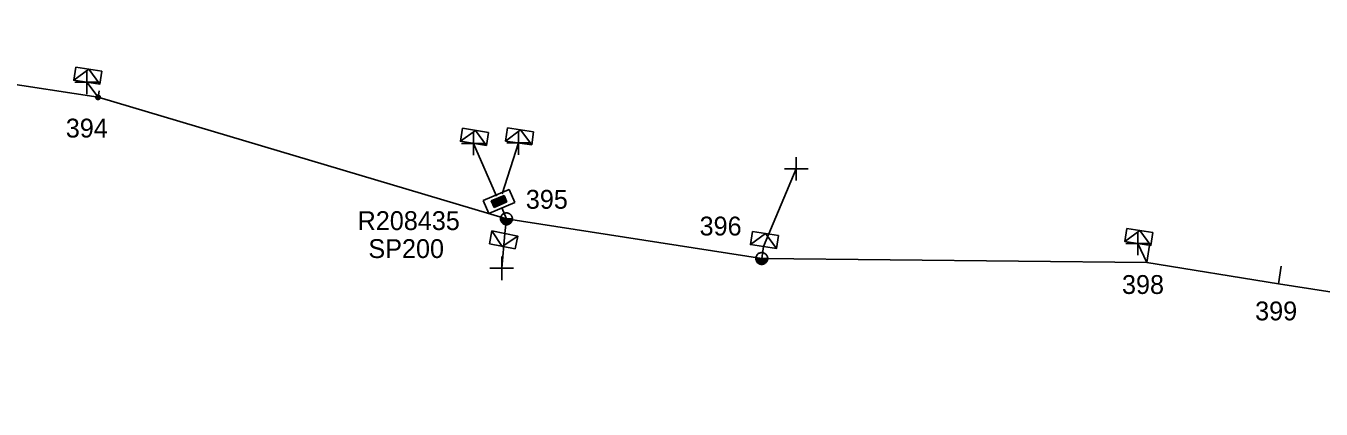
# Model space of a CAD drawing. Extents: x -540466 to -537383, y -1184038 to -1179972.
# Drawn here: x -539321 to -539252.2, y -1180550.2 to -1180529.9 of the extents above; entities that cross this region are included whole.
import ezdxf

# ---------------------------------------------------------------- set-up
doc = ezdxf.new("R2010")
doc.units = 0
for name, color, linetype in [('Vrstva 1', 7, 'Continuous'), ('Vrstva 13', 7, 'Continuous'), ('Vrstva 14', 7, 'Continuous'), ('Vrstva 2', 7, 'Continuous'), ('Vrstva 28', 7, 'Continuous'), ('Vrstva 29', 7, 'Continuous'), ('Vrstva 30', 7, 'Continuous'), ('Vrstva 31', 7, 'Continuous'), ('Vrstva 34', 7, 'Continuous'), ('Vrstva 50', 7, 'Continuous'), ('Vrstva 52', 7, 'Continuous'), ('Vrstva 54', 7, 'Continuous'), ('Vrstva 59', 7, 'Continuous'), ('Vrstva 8', 7, 'Continuous'), ('Vrstva 9', 7, 'Continuous')]:
    doc.layers.add(name, color=color, linetype=linetype)

# ---------------------------------------------------------------- blocks, each defined once
blk = doc.blocks.new('NN440')
at = {"layer": 'Vrstva 2'}
for points in [[(0.63, 0), (0.63, 0.06), (0.62, 0.13), (0.6, 0.19), (0.58, 0.25), (0.55, 0.31), (0.51, 0.37), (0.47, 0.42), (0.42, 0.46), (0.37, 0.51), (0.32, 0.54), (0.26, 0.57), (0.2, 0.59), (0.13, 0.61), (0.07, 0.62), (0, 0.63), (-0.06, 0.62), (-0.13, 0.61), (-0.19, 0.59), (-0.26, 0.57), (-0.31, 0.54), (-0.37, 0.51), (-0.42, 0.46), (-0.47, 0.42), (-0.51, 0.37), (-0.54, 0.31), (-0.57, 0.25), (-0.6, 0.19), (-0.62, 0.13), (-0.63, 0.06), (-0.63, 0), (-0.63, -0.07), (-0.62, -0.14), (-0.6, -0.2), (-0.57, -0.26), (-0.54, -0.32), (-0.51, -0.37), (-0.47, -0.43), (-0.42, -0.47), (-0.37, -0.51), (-0.31, -0.55), (-0.26, -0.58), (-0.19, -0.6), (-0.13, -0.62), (-0.06, -0.63), (0, -0.63), (0.07, -0.63), (0.13, -0.62), (0.2, -0.6), (0.26, -0.58), (0.32, -0.55), (0.37, -0.51), (0.42, -0.47), (0.47, -0.43), (0.51, -0.37), (0.55, -0.32), (0.58, -0.26), (0.6, -0.2), (0.62, -0.14), (0.63, -0.07), (0.63, 0)], [(-0.63, 0), (0.63, 0)], [(-0.6, -0.18), (0.57, -0.18)], [(-0.51, -0.32), (0.5, -0.32)], [(-0.37, -0.47), (0.35, -0.47)]]:
    blk.add_lwpolyline(points, dxfattribs=at)
blk = doc.blocks.new('NN800')
at = {"layer": 'Vrstva 1'}
for points in [[(-0.442, 0.442), (0.442, -0.442)], [(-0.442, -0.442), (0.442, 0.442)]]:
    blk.add_lwpolyline(points, dxfattribs=at)
blk = doc.blocks.new('NN620')
at = {"layer": 'Vrstva 8'}
for points in [[(0.752, 0.004), (-0.748, 0.004)], [(-0.748, 0.004), (-0.748, -0.746)], [(0.752, -0.746), (0.752, 0.004)], [(0.368, -0.18), (-0.376, -0.18)], [(-0.376, -0.18), (-0.376, -0.558)], [(-0.376, -0.558), (0.368, -0.558)], [(0.321, -0.227), (-0.329, -0.227)], [(-0.329, -0.227), (-0.329, -0.51)], [(-0.329, -0.51), (0.321, -0.51)], [(0.274, -0.274), (-0.281, -0.274)], [(-0.281, -0.274), (-0.281, -0.463)], [(-0.281, -0.463), (0.274, -0.463)], [(0.227, -0.321), (-0.234, -0.321)], [(-0.234, -0.321), (-0.234, -0.416)], [(-0.234, -0.416), (0.227, -0.416)], [(-0.193, -0.369), (0.185, -0.369)], [(0.227, -0.416), (0.227, -0.321)], [(0.274, -0.463), (0.274, -0.274)], [(0.321, -0.51), (0.321, -0.227)], [(0.368, -0.558), (0.368, -0.18)], [(-0.748, -0.746), (0.752, -0.746)]]:
    blk.add_lwpolyline(points, dxfattribs=at)
blk = doc.blocks.new('NN630')
at = {"layer": 'Vrstva 9'}
for points in [[(-0.003, -0.7), (-0.703, 0)], [(-0.703, -0.7), (-0.703, 0), (0.697, 0), (0.697, -0.7)], [(-0.003, -0.7), (0.697, 0)], [(-0.703, -0.7), (0.697, -0.7)]]:
    blk.add_lwpolyline(points, dxfattribs=at)
blk = doc.blocks.new('NN500')
at = {"layer": 'Vrstva 2'}
for points in [[(0, -0.24), (0.02, -0.23), (0.05, -0.23), (0.07, -0.22), (0.09, -0.22), (0.12, -0.2), (0.14, -0.19), (0.16, -0.18), (0.17, -0.16), (0.19, -0.14), (0.2, -0.12), (0.21, -0.1), (0.22, -0.07), (0.23, -0.05), (0.23, -0.02), (0.23, 0), (0.23, 0.02), (0.23, 0.05), (0.22, 0.07), (0.21, 0.1), (0.2, 0.12), (0.19, 0.14), (0.17, 0.16), (0.16, 0.17), (0.14, 0.19), (0.12, 0.2), (0.09, 0.21), (0.07, 0.22), (0.05, 0.23), (0.02, 0.23), (0, 0.23), (-0.03, 0.23), (-0.05, 0.23), (-0.07, 0.22), (-0.1, 0.21), (-0.12, 0.2), (-0.14, 0.19), (-0.16, 0.17), (-0.18, 0.16), (-0.19, 0.14), (-0.2, 0.12), (-0.22, 0.1), (-0.22, 0.07), (-0.23, 0.05), (-0.23, 0.02), (-0.24, 0), (-0.23, -0.02), (-0.23, -0.05), (-0.22, -0.07), (-0.22, -0.1), (-0.2, -0.12), (-0.19, -0.14), (-0.18, -0.16), (-0.16, -0.18), (-0.14, -0.19), (-0.12, -0.2), (-0.1, -0.22), (-0.07, -0.22), (-0.05, -0.23), (-0.03, -0.23), (0, -0.24)], [(0, -0.24), (0.02, -0.23), (0.05, -0.23), (0.07, -0.22), (0.09, -0.22), (0.12, -0.2), (0.14, -0.19), (0.16, -0.18), (0.17, -0.16), (0.19, -0.14), (0.2, -0.12), (0.21, -0.1), (0.22, -0.07), (0.23, -0.05), (0.23, -0.02), (0.23, 0), (0.23, 0.02), (0.23, 0.05), (0.22, 0.07), (0.21, 0.1), (0.2, 0.12), (0.19, 0.14), (0.17, 0.16), (0.16, 0.17), (0.14, 0.19), (0.12, 0.2), (0.09, 0.21), (0.07, 0.22), (0.05, 0.23), (0.02, 0.23), (0, 0.23), (-0.03, 0.23), (-0.05, 0.23), (-0.07, 0.22), (-0.1, 0.21), (-0.12, 0.2), (-0.14, 0.19), (-0.16, 0.17), (-0.18, 0.16), (-0.19, 0.14), (-0.2, 0.12), (-0.22, 0.1), (-0.22, 0.07), (-0.23, 0.05), (-0.23, 0.02), (-0.24, 0), (-0.23, -0.02), (-0.23, -0.05), (-0.22, -0.07), (-0.22, -0.1), (-0.2, -0.12), (-0.19, -0.14), (-0.18, -0.16), (-0.16, -0.18), (-0.14, -0.19), (-0.12, -0.2), (-0.1, -0.22), (-0.07, -0.22), (-0.05, -0.23), (-0.03, -0.23), (0, -0.24)], [(0, -0.21), (0.02, -0.2), (0.04, -0.2), (0.06, -0.2), (0.08, -0.19), (0.1, -0.18), (0.12, -0.17), (0.14, -0.15), (0.15, -0.14), (0.16, -0.12), (0.18, -0.1), (0.19, -0.08), (0.19, -0.06), (0.2, -0.04), (0.2, -0.02), (0.2, 0), (0.2, 0.02), (0.2, 0.04), (0.19, 0.06), (0.19, 0.08), (0.18, 0.1), (0.16, 0.12), (0.15, 0.14), (0.14, 0.15), (0.12, 0.17), (0.1, 0.18), (0.08, 0.19), (0.06, 0.19), (0.04, 0.2), (0.02, 0.2), (0, 0.2), (-0.02, 0.2), (-0.04, 0.2), (-0.06, 0.19), (-0.08, 0.19), (-0.1, 0.18), (-0.12, 0.17), (-0.14, 0.15), (-0.15, 0.14), (-0.17, 0.12), (-0.18, 0.1), (-0.19, 0.08), (-0.2, 0.06), (-0.2, 0.04), (-0.21, 0.02), (-0.21, 0), (-0.21, -0.02), (-0.2, -0.04), (-0.2, -0.06), (-0.19, -0.08), (-0.18, -0.1), (-0.17, -0.12), (-0.15, -0.14), (-0.14, -0.15), (-0.12, -0.17), (-0.1, -0.18), (-0.08, -0.19), (-0.06, -0.2), (-0.04, -0.2), (-0.02, -0.2), (0, -0.21)], [(0, -0.18), (0.02, -0.18), (0.04, -0.17), (0.05, -0.17), (0.07, -0.16), (0.09, -0.15), (0.1, -0.14), (0.12, -0.13), (0.13, -0.12), (0.14, -0.1), (0.15, -0.09), (0.16, -0.07), (0.17, -0.05), (0.17, -0.04), (0.17, -0.02), (0.17, 0), (0.17, 0.02), (0.17, 0.04), (0.17, 0.05), (0.16, 0.07), (0.15, 0.09), (0.14, 0.1), (0.13, 0.12), (0.12, 0.13), (0.1, 0.14), (0.09, 0.15), (0.07, 0.16), (0.05, 0.17), (0.04, 0.17), (0.02, 0.17), (0, 0.18), (-0.02, 0.17), (-0.04, 0.17), (-0.06, 0.17), (-0.07, 0.16), (-0.09, 0.15), (-0.1, 0.14), (-0.12, 0.13), (-0.13, 0.12), (-0.14, 0.1), (-0.15, 0.09), (-0.16, 0.07), (-0.17, 0.05), (-0.17, 0.04), (-0.18, 0.02), (-0.18, 0), (-0.18, -0.02), (-0.17, -0.04), (-0.17, -0.05), (-0.16, -0.07), (-0.15, -0.09), (-0.14, -0.1), (-0.13, -0.12), (-0.12, -0.13), (-0.1, -0.14), (-0.09, -0.15), (-0.07, -0.16), (-0.06, -0.17), (-0.04, -0.17), (-0.02, -0.18), (0, -0.18)], [(0, -0.15), (0.01, -0.15), (0.03, -0.14), (0.04, -0.14), (0.06, -0.13), (0.07, -0.13), (0.08, -0.12), (0.1, -0.11), (0.11, -0.1), (0.12, -0.09), (0.13, -0.07), (0.13, -0.06), (0.14, -0.05), (0.14, -0.03), (0.14, -0.02), (0.14, 0), (0.14, 0.01), (0.14, 0.03), (0.14, 0.04), (0.13, 0.06), (0.13, 0.07), (0.12, 0.09), (0.11, 0.1), (0.1, 0.11), (0.08, 0.12), (0.07, 0.13), (0.06, 0.13), (0.04, 0.14), (0.03, 0.14), (0.01, 0.14), (0, 0.15), (-0.02, 0.14), (-0.03, 0.14), (-0.05, 0.14), (-0.06, 0.13), (-0.07, 0.13), (-0.09, 0.12), (-0.1, 0.11), (-0.11, 0.1), (-0.12, 0.09), (-0.13, 0.07), (-0.13, 0.06), (-0.14, 0.04), (-0.14, 0.03), (-0.15, 0.01), (-0.15, 0), (-0.15, -0.02), (-0.14, -0.03), (-0.14, -0.05), (-0.13, -0.06), (-0.13, -0.07), (-0.12, -0.09), (-0.11, -0.1), (-0.1, -0.11), (-0.09, -0.12), (-0.07, -0.13), (-0.06, -0.13), (-0.05, -0.14), (-0.03, -0.14), (-0.02, -0.15), (0, -0.15)], [(0, -0.12), (0.01, -0.12), (0.02, -0.11), (0.03, -0.11), (0.05, -0.11), (0.06, -0.1), (0.07, -0.09), (0.08, -0.09), (0.09, -0.08), (0.09, -0.07), (0.1, -0.06), (0.11, -0.05), (0.11, -0.04), (0.11, -0.02), (0.11, -0.01), (0.12, 0), (0.11, 0.01), (0.11, 0.02), (0.11, 0.04), (0.11, 0.05), (0.1, 0.06), (0.09, 0.07), (0.09, 0.08), (0.08, 0.09), (0.07, 0.09), (0.06, 0.1), (0.05, 0.11), (0.03, 0.11), (0.02, 0.11), (0.01, 0.12), (0, 0.12), (-0.01, 0.12), (-0.03, 0.11), (-0.04, 0.11), (-0.05, 0.11), (-0.06, 0.1), (-0.07, 0.09), (-0.08, 0.09), (-0.09, 0.08), (-0.1, 0.07), (-0.1, 0.06), (-0.11, 0.05), (-0.11, 0.04), (-0.12, 0.02), (-0.12, 0.01), (-0.12, 0), (-0.12, -0.01), (-0.12, -0.02), (-0.11, -0.04), (-0.11, -0.05), (-0.1, -0.06), (-0.1, -0.07), (-0.09, -0.08), (-0.08, -0.09), (-0.07, -0.09), (-0.06, -0.1), (-0.05, -0.11), (-0.04, -0.11), (-0.03, -0.11), (-0.01, -0.12), (0, -0.12)], [(0, -0.09), (0.01, -0.09), (0.02, -0.09), (0.03, -0.08), (0.03, -0.08), (0.04, -0.08), (0.05, -0.07), (0.06, -0.07), (0.06, -0.06), (0.07, -0.05), (0.07, -0.04), (0.08, -0.04), (0.08, -0.03), (0.08, -0.02), (0.09, -0.01), (0.09, 0), (0.09, 0.01), (0.08, 0.02), (0.08, 0.03), (0.08, 0.03), (0.07, 0.04), (0.07, 0.05), (0.06, 0.06), (0.06, 0.06), (0.05, 0.07), (0.04, 0.07), (0.03, 0.08), (0.03, 0.08), (0.02, 0.08), (0.01, 0.09), (0, 0.09), (-0.01, 0.09), (-0.02, 0.08), (-0.03, 0.08), (-0.04, 0.08), (-0.04, 0.07), (-0.05, 0.07), (-0.06, 0.06), (-0.07, 0.06), (-0.07, 0.05), (-0.08, 0.04), (-0.08, 0.03), (-0.08, 0.03), (-0.09, 0.02), (-0.09, 0.01), (-0.09, 0), (-0.09, -0.01), (-0.09, -0.02), (-0.08, -0.03), (-0.08, -0.04), (-0.08, -0.04), (-0.07, -0.05), (-0.07, -0.06), (-0.06, -0.07), (-0.05, -0.07), (-0.04, -0.08), (-0.04, -0.08), (-0.03, -0.08), (-0.02, -0.09), (-0.01, -0.09), (0, -0.09)], [(0, -0.06), (0, -0.06), (0.01, -0.06), (0.02, -0.05), (0.02, -0.05), (0.03, -0.05), (0.03, -0.05), (0.04, -0.04), (0.04, -0.04), (0.05, -0.03), (0.05, -0.03), (0.05, -0.02), (0.05, -0.02), (0.05, -0.01), (0.06, -0.01), (0.06, 0), (0.06, 0.01), (0.05, 0.01), (0.05, 0.02), (0.05, 0.02), (0.05, 0.03), (0.05, 0.03), (0.04, 0.04), (0.04, 0.04), (0.03, 0.05), (0.03, 0.05), (0.02, 0.05), (0.02, 0.05), (0.01, 0.06), (0, 0.06), (0, 0.06), (-0.01, 0.06), (-0.01, 0.06), (-0.02, 0.05), (-0.02, 0.05), (-0.03, 0.05), (-0.03, 0.05), (-0.04, 0.04), (-0.04, 0.04), (-0.05, 0.03), (-0.05, 0.03), (-0.05, 0.02), (-0.06, 0.02), (-0.06, 0.01), (-0.06, 0.01), (-0.06, 0), (-0.06, -0.01), (-0.06, -0.01), (-0.06, -0.02), (-0.05, -0.02), (-0.05, -0.03), (-0.05, -0.03), (-0.04, -0.04), (-0.04, -0.04), (-0.03, -0.05), (-0.03, -0.05), (-0.02, -0.05), (-0.02, -0.05), (-0.01, -0.06), (-0.01, -0.06), (0, -0.06)], [(0, -0.03), (0, -0.03), (0, -0.03), (0.01, -0.03), (0.01, -0.03), (0.01, -0.02), (0.02, -0.02), (0.02, -0.02), (0.02, -0.02), (0.02, -0.02), (0.02, -0.01), (0.02, -0.01), (0.03, -0.01), (0.03, -0.01), (0.03, 0), (0.03, 0), (0.03, 0), (0.03, 0.01), (0.03, 0.01), (0.02, 0.01), (0.02, 0.01), (0.02, 0.02), (0.02, 0.02), (0.02, 0.02), (0.02, 0.02), (0.01, 0.02), (0.01, 0.02), (0.01, 0.03), (0, 0.03), (0, 0.03), (0, 0.03), (0, 0.03), (-0.01, 0.03), (-0.01, 0.03), (-0.01, 0.02), (-0.02, 0.02), (-0.02, 0.02), (-0.02, 0.02), (-0.02, 0.02), (-0.02, 0.02), (-0.03, 0.01), (-0.03, 0.01), (-0.03, 0.01), (-0.03, 0.01), (-0.03, 0), (-0.03, 0), (-0.03, 0), (-0.03, -0.01), (-0.03, -0.01), (-0.03, -0.01), (-0.03, -0.01), (-0.02, -0.02), (-0.02, -0.02), (-0.02, -0.02), (-0.02, -0.02), (-0.02, -0.02), (-0.01, -0.03), (-0.01, -0.03), (-0.01, -0.03), (0, -0.03), (0, -0.03)], [(0.23, 0), (0.7, 0)]]:
    blk.add_lwpolyline(points, dxfattribs=at)
blk = doc.blocks.new('NN510')
at = {"layer": 'Vrstva 2'}
blk.add_lwpolyline([(0.001, 0.002), (0.001, 0.939)], dxfattribs=at)

msp = doc.modelspace()

# ---------------------------------------------------------------- linework, layer by layer
at = {"layer": 'Vrstva 50'}
for points in [[(-539295.485, -1180540.145), (-539317.168, -1180533.702), (-539333.153, -1180531.261), (-539338.231, -1180530.182), (-539339.49, -1180529.914)], [(-539295.485, -1180540.145), (-539295.734, -1180539.567)], [(-539198.749, -1180541.928), (-539199.546, -1180542.493), (-539210.482, -1180550.242), (-539242.503, -1180545.452), (-539248.221, -1180544.572), (-539254.493, -1180543.594), (-539261.491, -1180542.471), (-539281.93, -1180542.25), (-539295.485, -1180540.145)]]:
    msp.add_lwpolyline(points, dxfattribs=at)
at = {"layer": 'Vrstva 52'}
for points in [[(-539296.008, -1180538.946), (-539297.241, -1180536.146)], [(-539295.716, -1180538.817), (-539294.84, -1180536.119)]]:
    msp.add_lwpolyline(points, dxfattribs=at)
at = {"layer": 'Vrstva 54'}
for points in [[(-539317.168, -1180533.702), (-539317.769, -1180532.906)], [(-539261.491, -1180542.471), (-539261.966, -1180541.455)]]:
    msp.add_lwpolyline(points, dxfattribs=at)
at = {"layer": 'Vrstva 59'}
for points in [[(-539281.843, -1180541.623), (-539280.099, -1180537.494)], [(-539295.564, -1180540.926), (-539295.737, -1180542.772)]]:
    msp.add_lwpolyline(points, dxfattribs=at)
at = {"layer": 'Vrstva 8'}
for points in [[(-539295.485, -1180540.145), (-539295.564, -1180540.926)], [(-539281.93, -1180542.25), (-539281.843, -1180541.623)]]:
    msp.add_lwpolyline(points, dxfattribs=at)

# ---------------------------------------------------------------- block references
at = {"layer": 'Vrstva 13'}
for name, p, xscale, yscale, rotation in [('NN500', (-539317.168, -1180533.702), 0.5, 0.5, 81.27300001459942), ('NN440', (-539281.93, -1180542.25), 0.4999999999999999, 0.5000000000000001, -0.617388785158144)]:
    msp.add_blockref(name, p, dxfattribs=dict(at, xscale=xscale, yscale=yscale, rotation=rotation))
at = {"layer": 'Vrstva 13', "xscale": 0.5, "yscale": 0.5}
msp.add_blockref('NN440', (-539295.485, -1180540.145), dxfattribs=at)
at = {"layer": 'Vrstva 13'}
for p, rotation in [((-539261.492, -1180542.472), -8.676172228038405), ((-539254.494, -1180543.595), -8.84317489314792)]:
    msp.add_blockref('NN510', p, dxfattribs=dict(at, rotation=rotation))
at = {"layer": 'Vrstva 28', "rotation": -156.66305842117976}
msp.add_blockref('NN620', (-539295.734, -1180539.567), dxfattribs=at)
at = {"layer": 'Vrstva 31'}
for p, rotation in [((-539317.769, -1180532.906), 171.2732500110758), ((-539297.241, -1180536.146), 170.8629056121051), ((-539294.84, -1180536.119), 171.90545558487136), ((-539295.564, -1180540.926), -11.233899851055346), ((-539281.843, -1180541.623), 171.1212305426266), ((-539261.966, -1180541.455), 171.32382778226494)]:
    msp.add_blockref('NN630', p, dxfattribs=dict(at, rotation=rotation))
at = {"layer": 'Vrstva 34'}
for p, rotation in [((-539317.769, -1180532.906), -45), ((-539297.241, -1180536.146), 44.99999995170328), ((-539294.84, -1180536.12), 45.000000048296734), ((-539280.099, -1180537.494), 45), ((-539261.966, -1180541.455), 45), ((-539295.737, -1180542.772), 45)]:
    msp.add_blockref('NN800', p, dxfattribs=dict(at, rotation=rotation))

# ---------------------------------------------------------------- texts
at = {"layer": 'Vrstva 14'}
for s, p in [('394', (-539318.881, -1180535.835)), ('395', (-539294.456, -1180539.614)), ('396', (-539285.23, -1180541.032)), ('398', (-539262.803, -1180544.134)), ('399', (-539255.734, -1180545.535))]:
    msp.add_text(s, height=1, dxfattribs=at).set_placement(p)
at = {"layer": 'Vrstva 29'}
msp.add_text('R208435', height=1, dxfattribs=at).set_placement((-539303.387, -1180540.744))
at = {"layer": 'Vrstva 30'}
msp.add_text('SP200', height=1, dxfattribs=at).set_placement((-539302.815, -1180542.228))

doc.saveas('drawing.dxf')
